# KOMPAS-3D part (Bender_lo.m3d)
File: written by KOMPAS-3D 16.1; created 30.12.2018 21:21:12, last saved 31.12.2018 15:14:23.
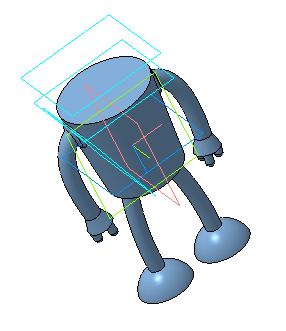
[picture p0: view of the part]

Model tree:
1. Эскиз:1
2. Операция вращения:1
     Угол 1 = 360
3. Эскиз:2
4. Операция выдавливания:1
     Расстояние 1 = 17.3; Угол 1 = 0.45
5. Скругление:1
     Радиус = 0.5
6. Скругление:2
     Радиус = 5
7. Смещенная плоскость:1
     Расстояние = 48
8. Эскиз:3
9. Вырезать элемент выдавливания:1
     Расстояние 1 = 10
10. Скругление:3
     Радиус = 5
11. Эскиз:4
12. Вырезать элемент выдавливания:2
     Расстояние 1 = 0.5
13. Эскиз:5
14. Операция вращения:2
     Угол 1 = 360
15. Эскиз:6
16. Операция вращения:3
     Угол 1 = 360
17. Эскиз:7
18. Эскиз:8
19. Кинематическая операция:1
20. Эскиз:9
21. Операция вращения:4
     Угол 1 = 360
22. Эскиз:10
23. Перпендикулярная плоскость:1
24. Эскиз:11
25. Кинематическая операция:2
26. Эскиз:12
27. Операция выдавливания:3
     Расстояние 1 = 7; Угол 1 = 20; Расстояние 2 = 0.5
28. Эскиз:13
29. Операция выдавливания:4
     Расстояние 1 = 7; Расстояние 2 = 0.5
30. Скругление:4
     Радиус = 2
31. Зеркальный массив:1
32. Экземпляр ( 1 )
33. Экземпляр ( 2 )  (with: Кинематическая операция:1, Операция вращения:4, Кинематическая операция:2, Операция выдавливания:3, Операция выдавливания:4, Скругление:4)
34. Смещенная плоскость:2
     Расстояние = 33
35. Сечение поверхностью:1

Referenced files in C:\Users\NIK\Desktop\: bender_bending_rodriguez_3d_model_c4d_max_obj_fbx_ma_lwo_3ds_3dm_stl_1135635_o.png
